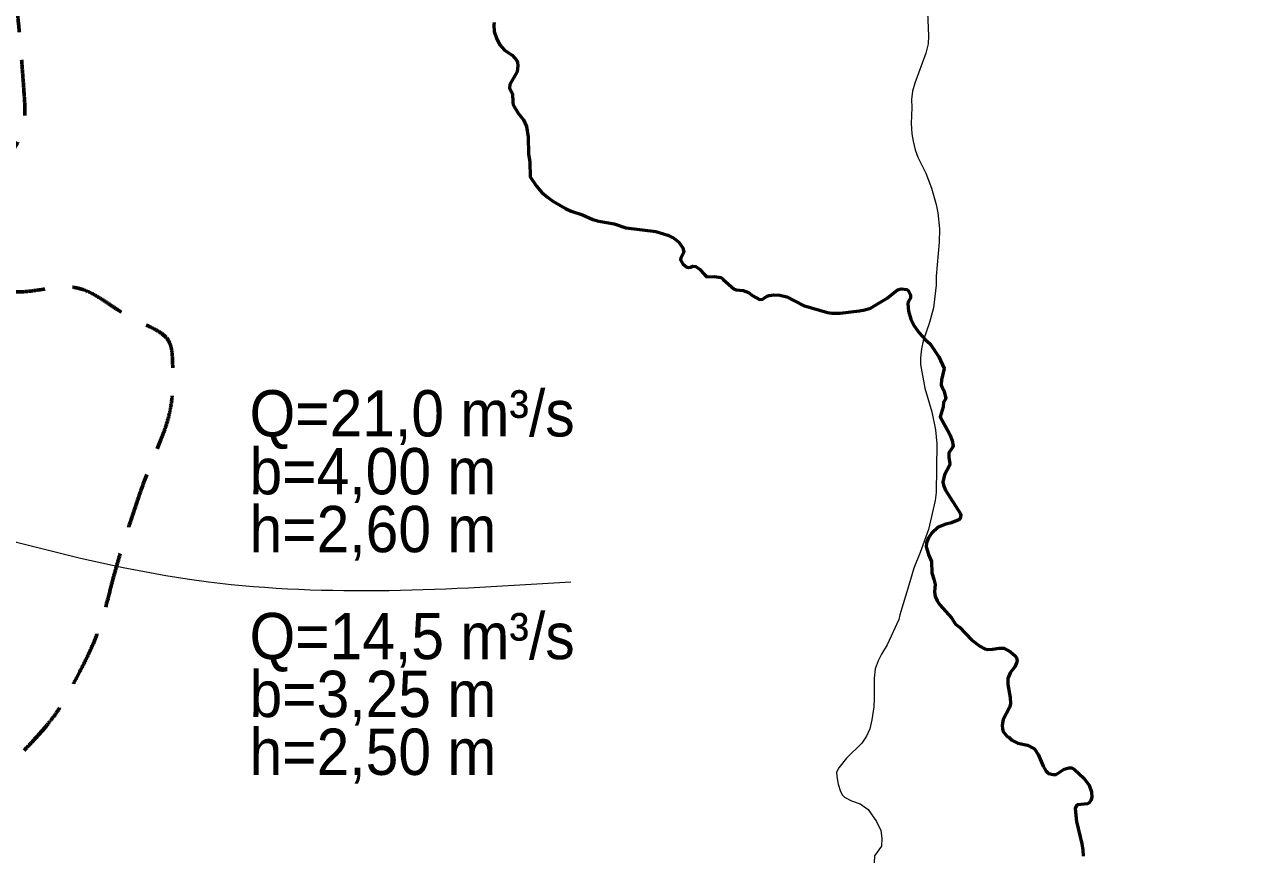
# Model space of a CAD drawing. Extents: x -1643653 to 4543381, y 1624270 to 13878484.
# Drawn here: x 752066 to 762553, y 8948961 to 8956206 of the extents above; entities that cross this region are included whole.
import ezdxf

# ---------------------------------------------------------------- set-up
doc = ezdxf.new("R2010")
doc.units = 0
doc.header["$LTSCALE"] = 160
doc.linetypes.add('MEDIUM_DASHED', pattern=[4.5, 3, -1.5])
for name, color, linetype, lineweight in [('10', 7, 'MEDIUM_DASHED', 60), ('14', 7, 'Continuous', 13), ('24', 7, 'Continuous', 25), ('50', 7, 'Continuous', 13), ('60', 7, 'Continuous', 13)]:
    doc.layers.add(name, color=color, linetype=linetype, lineweight=lineweight)

msp = doc.modelspace()

# ---------------------------------------------------------------- linework, layer by layer
at = {"layer": '10'}
msp.add_open_spline([(752064, 8949931.3), (752226.2, 8950099), (752371.1, 8950281.5), (752484, 8950494.8), (752727.4, 8950954.4), (752832, 8951444.1), (752990, 8951926.7), (753136.7, 8952374.9), (753359.2, 8952845.2), (753347.9, 8953290.8), (753342, 8953522.6), (753008.5, 8953646.6), (752804.9, 8953784.5), (752471.5, 8954010.4), (751900.3, 8953804.2), (751669.5, 8954179.5), (751384.3, 8954643.3), (752099.3, 8955128.6), (752064.4, 8955611.4), (752024.1, 8956168.6), (751963.7, 8956738.7), (751718.9, 8957290.2)], degree=3, dxfattribs=at)
at = {"layer": '14'}
for points in [[(759867.3, 8956445.9), (759879.8, 8956106.2), (759877.3, 8956037.4), (759858.6, 8955956.3), (759761.5, 8955697.4), (759741.8, 8955628.8), (759734.4, 8955555.9), (759735.8, 8955487.2), (759729.9, 8955349.5), (759736.2, 8955258.9), (759747.1, 8955195), (759765.6, 8955122.1), (759788.1, 8955057.4), (759856.1, 8954919.7), (759906.8, 8954790.2), (759947.4, 8954648.7), (759961.4, 8954575.8), (759976.4, 8954438.3), (759973.9, 8954322.7), (759947.5, 8954029.8), (759946, 8953952.7), (759923.2, 8953754.8), (759889.6, 8953629.9), (759834.2, 8953471.3), (759819.5, 8953402.5), (759811.3, 8953325.1), (759812.4, 8953265), (759848.2, 8953062.8), (759909.9, 8952856.4), (759942.4, 8952701.7), (759952.9, 8952580.2), (759946.5, 8952160.2), (759939.3, 8952091.6), (759880.8, 8951841.8), (759807.5, 8951640.4), (759753.1, 8951507.3), (759709.3, 8951360.8)], [(759709.3, 8951360.8), (759632, 8951102.5), (759624.2, 8951061.5), (759522.6, 8950843.3), (759474.2, 8950762.9), (759445.5, 8950706.2), (759419.9, 8950637.9), (759411.1, 8950557.2), (759411.4, 8950380.3), (759406.8, 8950307.6), (759392.1, 8950195), (759374.3, 8950118.4), (759344.4, 8950054), (759304, 8949993.2), (759170.9, 8949865.1), (759105.4, 8949780.7), (759086.2, 8949743.5), (759087.4, 8949705.1), (759098.4, 8949641.2), (759121.3, 8949577.4), (759137.2, 8949545.1), (759155.9, 8949527), (759216.2, 8949497.1), (759288.5, 8949470.6), (759360.2, 8949422), (759430.6, 8949317.8), (759467.5, 8949241.1), (759477.5, 8949172.3), (759475.1, 8949104), (759414.6, 8949021.4), (759409.5, 8948961.3)]]:
    msp.add_lwpolyline(points, dxfattribs=at)
at = {"layer": '24', "lineweight": 53}
for points in [[(756128.1, 8956221.2), (756124, 8956199.7), (756128.2, 8956143.1), (756146.9, 8956084.8), (756173.9, 8956031), (756217.2, 8955981.5), (756283.3, 8955940.1), (756321.8, 8955893.7), (756329.4, 8955877.8), (756331.8, 8955847), (756324.5, 8955795.2), (756263.6, 8955684.9), (756259.8, 8955654.5), (756286.7, 8955604.2), (756288.2, 8955533), (756292.5, 8955510.1), (756334.1, 8955437.5), (756380.4, 8955379.2), (756407.6, 8955324), (756421.1, 8955229.4), (756423.2, 8955087.5), (756434.1, 8955015.4), (756438.6, 8954889.2), (756493.2, 8954806.4), (756538.7, 8954753.6), (756587.5, 8954711), (756633.8, 8954677.4), (756743.5, 8954615), (756793.6, 8954592.1), (756890.4, 8954560.2), (756980.7, 8954519.9), (757031, 8954506.2), (757164, 8954481.5), (757264.8, 8954446.9), (757524.6, 8954416.7), (757626.7, 8954382.9), (757679.9, 8954358.9), (757723, 8954324.3), (757758.4, 8954274.9), (757765.6, 8954237.9), (757739.5, 8954184.8), (757736.2, 8954171.3), (757757.5, 8954135.5), (757791.8, 8954108), (757806.3, 8954104.2), (757824.5, 8954106), (757844.9, 8954115.1), (757869, 8954113.3), (757902.6, 8954091.2), (757943.8, 8954043.1), (757966.1, 8954024.2), (758029.9, 8954025.6), (758085, 8954017.8), (758101.3, 8954008.5)], [(758101.3, 8954008.5), (758106.9, 8953999.7), (758199.7, 8953917.6), (758218.4, 8953912.5), (758277.7, 8953907), (758325.5, 8953888.4), (758361.3, 8953858.8), (758419, 8953828.6), (758444.5, 8953830.4), (758487.6, 8953856), (758504.7, 8953862.3), (758544.9, 8953868.4), (758596.1, 8953866.1), (758654.8, 8953849.9), (758801, 8953777.3), (759008.6, 8953716.3), (759048.5, 8953710.9), (759118.3, 8953710.2), (759284.1, 8953730.2), (759331.6, 8953739.6), (759379.3, 8953754.1), (759522.6, 8953839.4), (759613.7, 8953910.2), (759644.3, 8953919), (759693.9, 8953913.5), (759706.3, 8953902.4), (759724.5, 8953867.6), (759724, 8953840.1), (759705.2, 8953806.7), (759701.8, 8953791.3), (759706.6, 8953728), (759727, 8953657.3), (759757.2, 8953601.2), (759799.2, 8953541), (759851.7, 8953481.5), (759893.5, 8953445.3), (759965.3, 8953342.1)], [(759965.3, 8953342.1), (759970.4, 8953332.8), (760015.5, 8953230.4), (759993.3, 8953133.4), (759989.8, 8953090.2), (759995.2, 8953072.2), (760012.7, 8953041.9), (760030.5, 8952976.2), (760028.6, 8952967.7), (760010.5, 8952941.3), (760006.7, 8952900.2), (759980.5, 8952814.3), (760064.6, 8952661.4), (760083.7, 8952610.4), (760092.8, 8952563.5), (760088.5, 8952550.5), (760057.5, 8952502.3), (760057.1, 8952461.6), (760064.8, 8952411), (760063.1, 8952393.2), (760019.9, 8952313.4), (760004.7, 8952250.6), (760010.5, 8952223.1), (760028.2, 8952180.1), (760153.6, 8951982.2), (760158.8, 8951968.6), (760154.4, 8951934.5), (760142.6, 8951924.2), (760078.6, 8951897.8), (760029, 8951887.2), (759964.9, 8951861.7), (759906.3, 8951805.3), (759880.4, 8951769.2), (759863.6, 8951724.3), (759860.3, 8951690), (759879.4, 8951623.6), (759905.1, 8951565), (759908.9, 8951466.9), (759927.6, 8951412), (759938.9, 8951364.3), (759933.3, 8951303), (759936.8, 8951260.5), (759955, 8951224.7), (759979.8, 8951190.2), (760080.6, 8951077.7), (760114.7, 8951023.7), (760149.7, 8950995.8), (760252.8, 8950886), (760322.7, 8950833.4), (760366, 8950810.2), (760393.2, 8950802.8), (760433.7, 8950805.5), (760491.5, 8950816), (760531.6, 8950814.5), (760588.5, 8950783.7), (760628.4, 8950748.2), (760642.2, 8950730.7), (760646.4, 8950707.4), (760641.5, 8950688.1), (760625.4, 8950655), (760584.9, 8950602), (760566, 8950552.7), (760567.4, 8950502.1), (760585.6, 8950389.3), (760588.6, 8950335.2)], [(760588.6, 8950335.2), (760579.4, 8950302.6), (760526.2, 8950197.8), (760517.9, 8950150.9), (760518.6, 8950115), (760524.8, 8950096.2), (760560.2, 8950052.5), (760573.6, 8950045.6), (760600.4, 8950021.6), (760652.6, 8949994.7), (760735.2, 8949978.4), (760796.3, 8949944.7), (760827, 8949897.8), (760870.5, 8949794.4), (760894.4, 8949756.4), (760917.9, 8949733), (760957.7, 8949723.4), (760983.8, 8949723)], [(760983.8, 8949723), (761052.1, 8949768.5), (761052.1, 8949768.5), (761093.2, 8949782.5), (761118.7, 8949782.5), (761143, 8949765.5), (761222.5, 8949692), (761270.1, 8949631.4), (761287.7, 8949575), (761290.9, 8949523.6), (761283.1, 8949497.5), (761268.7, 8949478.8), (761253.4, 8949469.9), (761168.1, 8949460.9), (761157.1, 8949449.3), (761149.4, 8949429.2), (761159.4, 8949316.6), (761205.6, 8949123.6), (761214.3, 8949072.6), (761216.9, 8949017.9)]]:
    msp.add_lwpolyline(points, dxfattribs=at)
at = {"layer": '24'}
for points in [[(756128.1, 8956221.2), (756124, 8956199.7), (756128.2, 8956143.1), (756146.9, 8956084.8), (756173.9, 8956031), (756217.2, 8955981.5), (756283.3, 8955940.1), (756321.8, 8955893.7), (756329.4, 8955877.8), (756331.8, 8955847), (756324.5, 8955795.2), (756263.6, 8955684.9), (756259.8, 8955654.5), (756286.7, 8955604.2), (756288.2, 8955533), (756292.5, 8955510.1), (756334.1, 8955437.5), (756380.4, 8955379.2), (756407.6, 8955324), (756421.1, 8955229.4), (756423.2, 8955087.5), (756434.1, 8955015.4), (756438.6, 8954889.2), (756493.2, 8954806.4), (756538.7, 8954753.6), (756587.5, 8954711), (756633.8, 8954677.4), (756743.5, 8954615), (756793.6, 8954592.1), (756890.4, 8954560.2), (756980.7, 8954519.9), (757031, 8954506.2), (757164, 8954481.5), (757264.8, 8954446.9), (757524.6, 8954416.7), (757626.7, 8954382.9), (757679.9, 8954358.9), (757723, 8954324.3), (757758.4, 8954274.9), (757765.6, 8954237.9), (757739.5, 8954184.8), (757736.2, 8954171.3), (757757.5, 8954135.5), (757791.8, 8954108), (757806.3, 8954104.2), (757824.5, 8954106), (757844.9, 8954115.1), (757869, 8954113.3), (757902.6, 8954091.2), (757943.8, 8954043.1), (757966.1, 8954024.2), (758029.9, 8954025.6), (758085, 8954017.8), (758101.3, 8954008.5)], [(758101.3, 8954008.5), (758106.9, 8953999.7), (758199.7, 8953917.6), (758218.4, 8953912.5), (758277.7, 8953907), (758325.5, 8953888.4), (758361.3, 8953858.8), (758419, 8953828.6), (758444.5, 8953830.4), (758487.6, 8953856), (758504.7, 8953862.3), (758544.9, 8953868.4), (758596.1, 8953866.1), (758654.8, 8953849.9), (758801, 8953777.3), (759008.6, 8953716.3), (759048.5, 8953710.9), (759118.3, 8953710.2), (759284.1, 8953730.2), (759331.6, 8953739.6), (759379.3, 8953754.1), (759522.6, 8953839.4), (759613.7, 8953910.2), (759644.3, 8953919), (759693.9, 8953913.5), (759706.3, 8953902.4), (759724.5, 8953867.6), (759724, 8953840.1), (759705.2, 8953806.7), (759701.8, 8953791.3), (759706.6, 8953728), (759727, 8953657.3), (759757.2, 8953601.2), (759799.2, 8953541), (759851.7, 8953481.5), (759893.5, 8953445.3), (759965.3, 8953342.1)], [(759965.3, 8953342.1), (759970.4, 8953332.8), (760015.5, 8953230.4), (759993.3, 8953133.4), (759989.8, 8953090.2), (759995.2, 8953072.2), (760012.7, 8953041.9), (760030.5, 8952976.2), (760028.6, 8952967.7), (760010.5, 8952941.3), (760006.7, 8952900.2), (759980.5, 8952814.3), (760064.6, 8952661.4), (760083.7, 8952610.4), (760092.8, 8952563.5), (760088.5, 8952550.5), (760057.5, 8952502.3), (760057.1, 8952461.6), (760064.8, 8952411), (760063.1, 8952393.2), (760019.9, 8952313.4), (760004.7, 8952250.6), (760010.5, 8952223.1), (760028.2, 8952180.1), (760153.6, 8951982.2), (760158.8, 8951968.6), (760154.4, 8951934.5), (760142.6, 8951924.2), (760078.6, 8951897.8), (760029, 8951887.2), (759964.9, 8951861.7), (759906.3, 8951805.3), (759880.4, 8951769.2), (759863.6, 8951724.3), (759860.3, 8951690), (759879.4, 8951623.6), (759905.1, 8951565), (759908.9, 8951466.9), (759927.6, 8951412), (759938.9, 8951364.3), (759933.3, 8951303), (759936.8, 8951260.5), (759955, 8951224.7), (759979.8, 8951190.2), (760080.6, 8951077.7), (760114.7, 8951023.7), (760149.7, 8950995.8), (760252.8, 8950886), (760322.7, 8950833.4), (760366, 8950810.2), (760393.2, 8950802.8), (760433.7, 8950805.5), (760491.5, 8950816), (760531.6, 8950814.5), (760588.5, 8950783.7), (760628.4, 8950748.2), (760642.2, 8950730.7), (760646.4, 8950707.4), (760641.5, 8950688.1), (760625.4, 8950655), (760584.9, 8950602), (760566, 8950552.7), (760567.4, 8950502.1), (760585.6, 8950389.3), (760588.6, 8950335.2)], [(760588.6, 8950335.2), (760579.4, 8950302.6), (760526.2, 8950197.8), (760517.9, 8950150.9), (760518.6, 8950115), (760524.8, 8950096.2), (760560.2, 8950052.5), (760573.6, 8950045.6), (760600.4, 8950021.6), (760652.6, 8949994.7), (760735.2, 8949978.4), (760796.3, 8949944.7), (760827, 8949897.8), (760870.5, 8949794.4), (760894.4, 8949756.4), (760917.9, 8949733), (760957.7, 8949723.4), (760983.8, 8949723)], [(760983.8, 8949723), (761052.1, 8949768.5), (761052.1, 8949768.5), (761093.2, 8949782.5), (761118.7, 8949782.5), (761143, 8949765.5), (761222.5, 8949692), (761270.1, 8949631.4), (761287.7, 8949575), (761290.9, 8949523.6), (761283.1, 8949497.5), (761268.7, 8949478.8), (761253.4, 8949469.9), (761168.1, 8949460.9), (761157.1, 8949449.3), (761149.4, 8949429.2), (761159.4, 8949316.6), (761205.6, 8949123.6), (761214.3, 8949072.6), (761216.9, 8949017.9)]]:
    msp.add_lwpolyline(points, dxfattribs=at)
at = {"layer": '50'}
msp.add_spline([(742378.1, 8951467.9), (744857.3, 8951843.2), (747806.2, 8952478.7), (753658.5, 8951389.2), (756788.8, 8951389.2)], degree=3, dxfattribs=at)
at = {"layer": '60', "lineweight": 25}
msp.add_spline([(814781, 9009175.5), (814787.2, 9009173.4), (814796.9, 9009173.4), (814799.4, 9009172.4), (814805.1, 9009174.5), (814805.6, 9009176.5), (814811.7, 9009179.5), (814811.7, 9009179.5), (814801.5, 9009181), (814790.7, 9009181.5), (814784.1, 9009183.1), (814777.4, 9009185.1), (814778.4, 9009175.5)], degree=3, dxfattribs=at)

# ---------------------------------------------------------------- texts
at = {"layer": '50', "width": 0.95}
for s, p in [('Q=21,0 m³/s', (754013, 8952644.5)), ('b=4,00 m', (754013, 8952144.5)), ('h=2,60 m', (754013, 8951644.5)), ('Q=14,5 m³/s', (754013, 8950720)), ('b=3,25 m', (754013, 8950220)), ('h=2,50 m', (754013, 8949720))]:
    msp.add_text(s, height=400, dxfattribs=at).set_placement(p)

doc.saveas('drawing.dxf')
